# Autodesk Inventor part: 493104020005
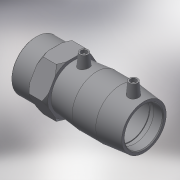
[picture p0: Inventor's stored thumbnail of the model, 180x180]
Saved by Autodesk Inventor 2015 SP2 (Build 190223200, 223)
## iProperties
Created: 2017-06
Part Number: 493104020005
Material: Generic
Description: PLASSON FEMALE TRANSITION COUPLER 20-1/2"
Document SubType Name: Modeling
Designer: KIM
Mass: 52.916 g
Surface Area: 188.951 cm^2
Volume: 52.916 cm^3
Density: 1 g/cm^3
Appearance: Default
Author: KIM
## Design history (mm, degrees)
derived "493104.ipt"
feature "Solid1::493104.ipt"
tag "TaggingFeature1"
body "Solid1"
other parameters: "d0" = 76, "d2" = 31, "d3" = 37, "d4" = 25.33333, "d5" = 27.9, "d6" = 19, "d8" = 168 deg, "d10" = 14.8, "d11" = 4.93333, "d29" = 35, "d30" = 14, "d31" = 26.6, "d34" = 5 deg, "d41" = 4, "d42" = 14, "d43" = 0, "d48" = 3, "d49" = 0, "d57" = 14, "d59" = 18.631, "d60" = 18, "d70" = 31, "d72" = 0, "d73" = 45 deg, "d74" = 1.4, "d75" = 45 deg, "d77" = 0.3, "d80" = 0.4, "L_" = 96, "L_1" = 37, "D_1" = 31, "A_" = 35, "d_2" = 12, "D_" = 14, "R_p" = 18.631
